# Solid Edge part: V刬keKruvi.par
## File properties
Author: Egon 815
Template: Normal.par
Last saved by: Egon 815
Revision: 15
Application: Solid Edge
Accuracy: 0,99
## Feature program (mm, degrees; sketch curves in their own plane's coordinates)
sketch for "unnamed Protrusion 1" plane through (0, 0, 0) normal (0, -1, 0) x-axis (1, 0, 0)
  circle centre (0, 0) radius 40
extrude "unnamed Protrusion 1" add
sketch for "unnamed RevolvedProtrusion 1" plane through (0, 0, 0) normal (1, 0, 0) x-axis (0, 1, 0)
  line (40, 210) -> (-40, 210)
revolve "unnamed RevolvedProtrusion 1" add
sketch for "unnamed Cutout 1" plane through (0, 0, 0) normal (0, 0, 1) x-axis (1, 0, 0)
  line (-210, 40) -> (210, 40)
extrude "unnamed Cutout 1" cut
fillet "Round_1" radius 40
lofted protrusion "LoftedProtrusion_21"
sketch for "ExtrudedProtrusion_2" plane through (168.0192, 0, 163.638) normal (0.818581, 0, 0.574392) x-axis (0, -1, 0)
  circle centre (-2.857, 21.059) radius 5
extrude "ExtrudedProtrusion_2" add
fillet "Round_5" radius 5
pattern "unnamed Pattern 1" of "LoftedProtrusion_21"
lofted protrusion "unnamed LoftedProtrusion 1"
lofted protrusion "unnamed LoftedProtrusion 2"
lofted protrusion "unnamed LoftedProtrusion 3"
lofted protrusion "unnamed LoftedProtrusion 4"
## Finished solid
Body 1: solid body, 13 faces, 36 edges, 30 vertices.
  Faces by surface: plane 5, spline 5, sphere 2, cylinder 1
  Edges by curve: circle 26, intersection 10
Bounding box of the edges (mm; curved faces can reach further): 429.748 x 174.124 x 443.938, from (-231.8501, -150, -225.9319) to (197.898, 24.1241, 218.0064).
Cylindrical faces by radius (mm): R40 x1
Spherical faces by radius (mm): R5 x1, R40 x1
Planar faces by outward normal: -y 1, oblique 4
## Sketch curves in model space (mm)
circle centre (180.1154, 2.857, 146.3995) radius 5
line (-210, 40, 0) -> (210, 40, 0)
arc centre (38.2683, -10, 92.388) radius 15 from (51.5954, -14.1131, 86.8677) through (32.9885, -23.8687, 94.5749) to (26.1331, -2.7565, 97.4145)
arc centre (87.1341, -25.0813, 72.1471) radius 40 from (86.0156, 14.9004, 72.6104) through (64.4281, 6.4778, 81.5522) to (51.5954, -14.1131, 86.8677)
arc centre (85.8478, 20.8976, 72.6799) radius 6 from (87.0894, 26.7452, 72.1656) through (91.3232, 19.9613, 70.4119) to (86.0156, 14.9004, 72.6104)
arc centre (74.6741, -31.7306, 77.3082) radius 60 from (26.1331, -2.7565, 97.4145) through (52.0469, 23.0432, 86.6807) to (87.0894, 26.7452, 72.1656)
arc centre (141.4214, -10, 141.4214) radius 18 from (154.0375, -7.6192, 128.8053) through (138.9942, -27.6697, 143.8485) to (129.688, -3.0247, 153.1547)
arc centre (182.0732, -2.3285, 100.7695) radius 40 from (157.0355, 16.2786, 125.8072) through (154.2239, 4.659, 128.6188) to (154.0375, -7.6192, 128.8053)
arc centre (152.028, 20, 130.8148) radius 8 from (149.4478, 27.1193, 133.395) through (156.2752, 25.2841, 126.5675) to (157.0355, 16.2786, 125.8072)
arc centre (168.7993, -26.2758, 114.0435) radius 60 from (129.688, -3.0247, 153.1547) through (137.6856, 14.515, 145.1571) to (149.4478, 27.1193, 133.395)
arc centre (0, -10, 0) radius 12 from (11.9938, -10.3844, 0) through (-3.0374, -21.6092, 0) to (-10.9574, -5.1076, 0)
arc centre (51.9733, -11.6655, 0) radius 40 from (23.5526, 16.4816, 0) through (15.2297, 4.1429, 0) to (11.9938, -10.3844, 0)
arc centre (20, 20, 0) radius 5 from (17.8337, 24.5063, 0) through (24.1564, 22.7793, 0) to (23.5526, 16.4816, 0)
arc centre (43.8295, -29.5697, 0) radius 60 from (-10.9574, -5.1076, 0) through (0.8097, 12.2548, 0) to (17.8337, 24.5063, 0)
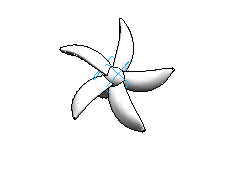
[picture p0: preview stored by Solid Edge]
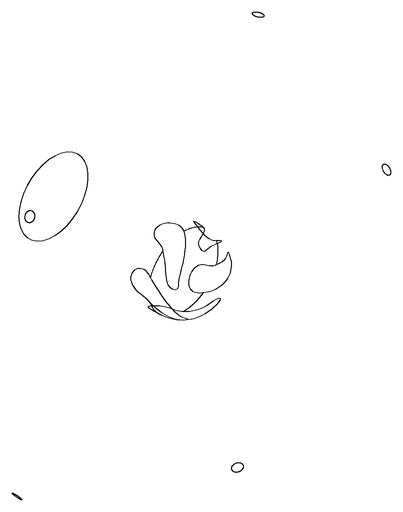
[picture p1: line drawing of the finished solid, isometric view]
